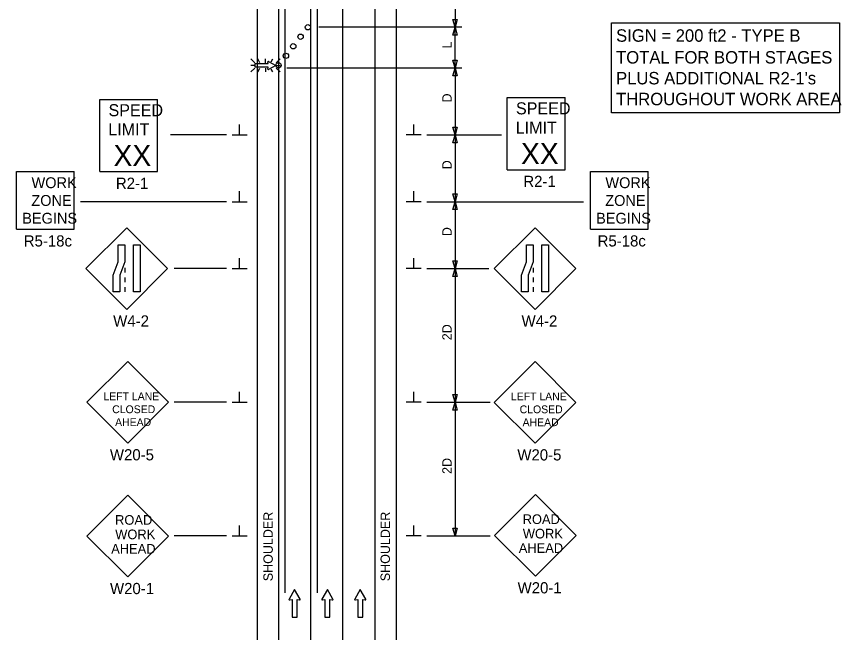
# Model space of a CAD drawing. Extents: x 16782 to 19504, y 6935 to 8243.
# Drawn here: x 16795 to 17412, y 7395 to 7856 of the extents above; entities that cross this region are included whole.
import ezdxf

# ---------------------------------------------------------------- set-up
doc = ezdxf.new("R2010")
doc.units = 0
for name, color, linetype in [('ALI_LEGAL_EX', 7, 'Continuous'), ('MT_SCRATCH_LEVEL_E', 7, 'Continuous'), ('PAVT_EDGE_EX', 7, 'Continuous'), ('TRAFFIC_SIGNS_PR', 7, 'Continuous'), ('TYPICAL_TEXT_DIMEN_EX', 7, 'Continuous'), ('TYPICAL_TEXT_DIMEN_PR', 7, 'Continuous')]:
    doc.layers.add(name, color=color, linetype=linetype)

msp = doc.modelspace()

# ---------------------------------------------------------------- linework, layer by layer
at = {"layer": 'ALI_LEGAL_EX'}
for p, q in [((16995.95, 8243.16), (16995.95, 7425.02)), ((17019.95, 8243.16), (17019.95, 7425.02))]:
    msp.add_line(p, q, dxfattribs=at)
for points in [[(17015.15, 7783.87), (17015.15, 7758.87)], [(17039.15, 7758.87), (17039.15, 7783.87)], [(17015.15, 7683.87), (17015.15, 7658.87)], [(17039.15, 7658.87), (17039.15, 7683.87)], [(17015.15, 7583.87), (17015.15, 7558.87)], [(17039.15, 7558.87), (17039.15, 7583.87)], [(17015.15, 7483.87), (17015.15, 7458.87)], [(17039.15, 7458.87), (17039.15, 7483.87)]]:
    msp.add_lwpolyline(points, dxfattribs=at)
at = {"layer": 'MT_SCRATCH_LEVEL_E'}
for p, q in [((17003.12, 7427.51), (16999.01, 7420.27)), ((17007.27, 7420.27), (17003.12, 7427.51)), ((17027.68, 7427.51), (17023.57, 7420.27)), ((17031.83, 7420.27), (17027.68, 7427.51)), ((17052.24, 7427.51), (17048.13, 7420.27)), ((17056.39, 7420.27), (17052.24, 7427.51)), ((16999.49, 7419.59), (17001.27, 7419.9)), ((17001.27, 7419.9), (17001.27, 7406.65)), ((17005.01, 7406.65), (17005.01, 7419.9)), ((17005.01, 7419.9), (17006.79, 7419.59)), ((17024.05, 7419.59), (17025.83, 7419.9)), ((17025.83, 7419.9), (17025.83, 7406.65)), ((17029.57, 7406.65), (17029.57, 7419.9)), ((17029.57, 7419.9), (17031.35, 7419.59)), ((17048.61, 7419.59), (17050.39, 7419.9)), ((17050.39, 7419.9), (17050.39, 7406.65)), ((17054.13, 7406.65), (17054.13, 7419.9)), ((17054.13, 7419.9), (17055.91, 7419.59)), ((17001.27, 7406.65), (17005.01, 7406.65)), ((17025.83, 7406.65), (17029.57, 7406.65)), ((17050.39, 7406.65), (17054.13, 7406.65))]:
    msp.add_line(p, q, dxfattribs=at)
for centre, start, end in [((16999.42, 7420.05), 150.42484, 279.96381), ((17006.86, 7420.05), 260.03619, 29.77312), ((17023.98, 7420.05), 150.42484, 279.96381), ((17031.42, 7420.05), 260.03619, 29.77312), ((17048.54, 7420.05), 150.42484, 279.96381), ((17055.98, 7420.05), 260.03619, 29.77312)]:
    msp.add_arc(centre, 0.463, start, end, dxfattribs=at)
at = {"layer": 'PAVT_EDGE_EX'}
for p, q in [((16975.15, 8208.67), (16975.15, 7354.69)), ((16991.15, 8208.67), (16991.15, 7354.69)), ((17063.15, 8208.67), (17063.15, 7354.69)), ((17079.15, 8208.67), (17079.15, 7354.69)), ((17015.15, 8183.87), (17015.15, 7354.69)), ((17039.15, 7358.87), (17039.15, 8183.87))]:
    msp.add_line(p, q, dxfattribs=at)
at = {"layer": 'TRAFFIC_SIGNS_PR'}
for p, q in [((16973.31, 7821.47), (16970.49, 7824.29)), ((16977.26, 7821.47), (16975.64, 7824.28)), ((16981.4, 7821.47), (16981.4, 7824.28)), ((16985.58, 7822.1), (16986.84, 7824.28)), ((16992.3, 7824.28), (16989.49, 7821.47)), ((16973.31, 7819.43), (16970.49, 7819.43)), ((16973.31, 7817.4), (16970.49, 7814.58)), ((16975.61, 7814.58), (16977.24, 7817.4)), ((16981.4, 7817.4), (16981.4, 7814.58)), ((16986.87, 7814.58), (16985.66, 7816.67)), ((16989.49, 7819.43), (16992.3, 7819.43)), ((16992.3, 7814.58), (16989.49, 7817.4)), ((16857.53, 7794.02), (16900.73, 7794.02)), ((16857.53, 7740.02), (16857.53, 7794.02)), ((16900.73, 7740.02), (16900.73, 7794.02)), ((17162.19, 7795.41), (17205.39, 7795.41)), ((17162.19, 7741.41), (17162.19, 7795.41)), ((17205.39, 7741.41), (17205.39, 7795.41)), ((16795.22, 7696.88), (16795.22, 7740.08)), ((16795.22, 7740.08), (16838.42, 7740.08)), ((16838.42, 7696.88), (16838.42, 7740.08)), ((16857.53, 7740.02), (16900.73, 7740.02)), ((17162.19, 7741.41), (17205.39, 7741.41)), ((17224.31, 7696.88), (17224.31, 7740.08)), ((17224.31, 7740.08), (17267.51, 7740.08)), ((17267.51, 7696.88), (17267.51, 7740.08)), ((16795.22, 7696.88), (16838.42, 7696.88)), ((16877.68, 7698.1), (16847.14, 7667.55)), ((16908.23, 7667.55), (16877.68, 7698.1)), ((17183.04, 7698.05), (17152.49, 7667.5)), ((17213.58, 7667.5), (17183.04, 7698.05)), ((17224.31, 7696.88), (17267.51, 7696.88)), ((16876.28, 7668.1), (16876.28, 7664.5)), ((17181.63, 7668.05), (17181.63, 7664.45)), ((16847.14, 7667.55), (16877.68, 7637)), ((16877.68, 7637), (16908.23, 7667.55)), ((17152.49, 7667.5), (17183.04, 7636.95)), ((17183.04, 7636.95), (17213.58, 7667.5)), ((16876.28, 7660.9), (16876.28, 7657.3)), ((17181.63, 7660.85), (17181.63, 7657.25)), ((16876.28, 7653.7), (16876.28, 7650.1)), ((17181.63, 7653.65), (17181.63, 7650.05)), ((16878.35, 7598), (16847.8, 7567.45)), ((16908.89, 7567.45), (16878.35, 7598)), ((17183.02, 7597.93), (17152.47, 7567.38)), ((17213.57, 7567.38), (17183.02, 7597.93)), ((16847.8, 7567.45), (16878.35, 7536.9)), ((16878.35, 7536.9), (16908.89, 7567.45)), ((17152.47, 7567.38), (17183.02, 7536.83)), ((17183.02, 7536.83), (17213.57, 7567.38)), ((16878.44, 7497.94), (16847.89, 7467.39)), ((16908.98, 7467.39), (16878.44, 7497.94)), ((17183.22, 7498.49), (17152.67, 7467.94)), ((17213.76, 7467.94), (17183.22, 7498.49)), ((16847.89, 7467.39), (16878.44, 7436.85)), ((16878.44, 7436.85), (16908.98, 7467.39)), ((17152.67, 7467.94), (17183.22, 7437.4)), ((17183.22, 7437.4), (17213.76, 7467.94))]:
    msp.add_line(p, q, dxfattribs=at)
for points in [[(16983.73, 7822.45), (16989.04, 7819.43), (16983.73, 7816.39)], [(16983.23, 7816.75), (16983.46, 7818.05), (16973.73, 7818.05), (16973.73, 7820.79), (16983.46, 7820.79), (16983.22, 7822.09)]]:
    msp.add_lwpolyline(points, dxfattribs=at)
for points in [[(16876.28, 7685.25), (16876.28, 7672.67), (16872.52, 7662.68), (16872.52, 7650.1), (16867.46, 7650.1), (16867.46, 7662.68), (16871.23, 7672.67), (16871.23, 7685.25)], [(16887.68, 7685.25), (16887.68, 7650.1), (16882.63, 7650.1), (16882.63, 7685.25)], [(17181.63, 7685.21), (17181.63, 7672.63), (17177.87, 7662.63), (17177.87, 7650.05), (17172.81, 7650.05), (17172.81, 7662.63), (17176.58, 7672.63), (17176.58, 7685.21)], [(17193.04, 7685.21), (17193.04, 7650.05), (17187.98, 7650.05), (17187.98, 7685.21)]]:
    msp.add_lwpolyline(points, close=True, dxfattribs=at)
for centre in [(17013.14, 7848.04), (17013.14, 7848.04), (17013.14, 7848.04), (17013.14, 7848.04), (17007.65, 7840.91), (17002.15, 7833.78), (16996.65, 7826.65), (16991.15, 7819.53)]:
    msp.add_circle(centre, 2, dxfattribs=at)
for centre, start, end in [((16983.56, 7822.15), 61.10835, 189.26922), ((16983.56, 7816.69), 170.04067, 298.51671)]:
    msp.add_arc(centre, 0.341, start, end, dxfattribs=at)
at = {"layer": 'TYPICAL_TEXT_DIMEN_EX'}
msp.add_lwpolyline([(17240.11, 7851.23), (17410.53, 7851.23), (17410.53, 7784.05), (17240.11, 7784.05)], close=True, dxfattribs=at)
at = {"layer": 'TYPICAL_TEXT_DIMEN_PR'}
for p, q in [((17123.24, 7940.1), (17123.15, 7848.04)), ((17123.15, 7848.04), (17121.58, 7853.9)), ((17121.58, 7853.9), (17123.15, 7853.9)), ((17123.15, 7853.9), (17124.72, 7853.9)), ((17124.72, 7853.9), (17123.15, 7848.04)), ((17128.15, 7848.04), (17021.23, 7848.04)), ((17121.58, 7842.18), (17123.15, 7848.04)), ((17123.15, 7817.53), (17123.15, 7848.04)), ((17123.15, 7848.04), (17124.72, 7842.18)), ((17123.15, 7842.18), (17121.58, 7842.18)), ((17124.72, 7842.18), (17123.15, 7842.18)), ((17123.15, 7817.53), (17121.58, 7823.39)), ((17121.58, 7823.39), (17123.15, 7823.39)), ((17123.15, 7823.39), (17124.72, 7823.39)), ((17124.72, 7823.39), (17123.15, 7817.53)), ((17128.15, 7817.53), (16997.42, 7817.53)), ((17121.58, 7811.67), (17123.15, 7817.53)), ((17123.15, 7817.53), (17123.15, 7767.53)), ((17123.15, 7817.53), (17124.72, 7811.67)), ((17123.15, 7811.67), (17121.58, 7811.67)), ((17124.72, 7811.67), (17123.15, 7811.67)), ((16962.03, 7767.53), (16962.03, 7775.31)), ((17092.28, 7767.53), (17092.28, 7775.31)), ((17123.15, 7767.53), (17121.58, 7773.39)), ((17121.58, 7773.39), (17123.15, 7773.39)), ((17123.15, 7773.39), (17124.72, 7773.39)), ((17124.72, 7773.39), (17123.15, 7767.53)), ((16952.15, 7767.53), (16910.46, 7767.53)), ((16956.4, 7767.53), (16967.65, 7767.53)), ((17097.9, 7767.53), (17086.65, 7767.53)), ((17102.15, 7767.53), (17157.89, 7767.53)), ((17121.58, 7761.67), (17123.15, 7767.53)), ((17123.15, 7767.53), (17124.72, 7761.67)), ((17123.15, 7767.53), (17123.15, 7717.53)), ((17123.15, 7761.67), (17121.58, 7761.67)), ((17124.72, 7761.67), (17123.15, 7761.67)), ((16962.03, 7717.53), (16962.03, 7725.31)), ((17092.28, 7717.53), (17092.28, 7725.31)), ((16952.15, 7717.53), (16843.19, 7717.53)), ((16956.4, 7717.53), (16967.65, 7717.53)), ((17097.9, 7717.53), (17086.65, 7717.53)), ((17102.15, 7717.53), (17219.11, 7717.53)), ((17123.15, 7717.53), (17121.58, 7723.39)), ((17121.58, 7723.39), (17123.15, 7723.39)), ((17121.58, 7711.67), (17123.15, 7717.53)), ((17123.15, 7723.39), (17124.72, 7723.39)), ((17124.72, 7723.39), (17123.15, 7717.53)), ((17123.15, 7717.53), (17124.72, 7711.67)), ((17123.15, 7717.53), (17123.15, 7667.53)), ((17123.15, 7711.67), (17121.58, 7711.67)), ((17124.72, 7711.67), (17123.15, 7711.67)), ((16962.03, 7667.53), (16962.03, 7675.31)), ((17092.28, 7667.53), (17092.28, 7675.31)), ((17123.15, 7667.53), (17121.58, 7673.39)), ((17121.58, 7673.39), (17123.15, 7673.39)), ((17123.15, 7673.39), (17124.72, 7673.39)), ((17124.72, 7673.39), (17123.15, 7667.53)), ((16952.15, 7667.53), (16913.15, 7667.53)), ((16956.4, 7667.53), (16967.65, 7667.53)), ((17097.9, 7667.53), (17086.65, 7667.53)), ((17102.15, 7667.53), (17148.41, 7667.53)), ((17121.58, 7661.67), (17123.15, 7667.53)), ((17123.15, 7667.53), (17123.15, 7567.53)), ((17123.15, 7667.53), (17124.72, 7661.67)), ((17123.15, 7661.67), (17121.58, 7661.67)), ((17124.72, 7661.67), (17123.15, 7661.67)), ((16962.03, 7567.53), (16962.03, 7575.31)), ((17092.28, 7567.53), (17092.28, 7575.31)), ((17123.15, 7567.53), (17121.58, 7573.39)), ((17121.58, 7573.39), (17123.15, 7573.39)), ((17123.15, 7573.39), (17124.72, 7573.39)), ((17124.72, 7573.39), (17123.15, 7567.53)), ((16952.15, 7567.53), (16913.15, 7567.53)), ((16956.4, 7567.53), (16967.65, 7567.53)), ((17097.9, 7567.53), (17086.65, 7567.53)), ((17102.15, 7567.53), (17149.45, 7567.53)), ((17121.58, 7561.67), (17123.15, 7567.53)), ((17123.15, 7567.53), (17123.15, 7467.53)), ((17123.15, 7567.53), (17124.72, 7561.67)), ((17123.15, 7561.67), (17121.58, 7561.67)), ((17124.72, 7561.67), (17123.15, 7561.67)), ((16962.03, 7467.53), (16962.03, 7475.31)), ((17092.28, 7467.53), (17092.28, 7475.31)), ((17123.15, 7467.53), (17121.58, 7473.39)), ((17121.58, 7473.39), (17123.15, 7473.39)), ((17123.15, 7473.39), (17124.72, 7473.39)), ((17124.72, 7473.39), (17123.15, 7467.53)), ((16952.15, 7467.53), (16913.15, 7467.53)), ((16956.4, 7467.53), (16967.65, 7467.53)), ((17097.9, 7467.53), (17086.65, 7467.53)), ((17102.15, 7467.53), (17149.45, 7467.53))]:
    msp.add_line(p, q, dxfattribs=at)

# ---------------------------------------------------------------- texts
at = {"layer": 'TRAFFIC_SIGNS_PR'}
for s, height, p in [('SPEED', 9, (17168.68, 7782.87)), ('SPEED', 9, (16864.02, 7781.49)), ('LIMIT', 9, (16863.84, 7767.09)), ('LIMIT', 9, (17168.5, 7768.47)), ('XX', 15.785, (17172.44, 7745.63)), ('XX', 15.785, (16867.78, 7744.25)), ('WORK', 8.119, (16806.46, 7727.67)), ('R2-1', 8.37, (17174.2, 7728.54)), ('WORK', 8.119, (17235.56, 7727.67)), ('R2-1', 8.37, (16869.54, 7727.15)), ('ZONE', 8.119, (16806.33, 7714.38)), ('ZONE', 8.119, (17235.43, 7714.38)), ('BEGINS', 8.119, (16799.5, 7701.1)), ('BEGINS', 8.119, (17228.6, 7701.1)), ('R5-18c', 8.37, (16800.63, 7684.01)), ('R5-18c', 8.37, (17229.73, 7684.01)), ('W4-2', 8.37, (16867.51, 7624.13)), ('W4-2', 8.37, (17172.86, 7624.09)), ('LEFT LANE', 5.85, (16860.21, 7569.02)), ('LEFT LANE', 5.85, (17164.89, 7568.95)), ('CLOSED', 5.85, (16866.77, 7559.34)), ('CLOSED', 5.85, (17171.45, 7559.27)), ('AHEAD', 5.85, (16868.96, 7549.67)), ('AHEAD', 5.85, (17173.64, 7549.6)), ('W20-5', 8.37, (16865.04, 7524.03)), ('W20-5', 8.37, (17169.71, 7523.96)), ('ROAD', 7.2, (16868.92, 7475.87)), ('ROAD', 7.2, (17173.7, 7476.42)), ('WORK', 7.2, (16869.04, 7465.07)), ('WORK', 7.2, (17173.82, 7465.62)), ('AHEAD', 7.2, (16866.02, 7454.27)), ('AHEAD', 7.2, (17170.8, 7454.82)), ('W20-1', 8.37, (16865.13, 7423.98)), ('W20-1', 8.37, (17169.91, 7424.53))]:
    msp.add_text(s, height=height, dxfattribs=at).set_placement(p)
at = {"layer": 'TYPICAL_TEXT_DIMEN_EX'}
for s, p in [('SIGN = 200 ft2 - TYPE B', (17243.55, 7837.19)), ('TOTAL FOR BOTH STAGES', (17243.55, 7820.89)), ("PLUS ADDITIONAL R2-1's", (17243.55, 7805.29)), ('THROUGHOUT WORK AREA', (17243.55, 7789.69))]:
    msp.add_text(s, height=9.3, dxfattribs=at).set_placement(p)
at = {"layer": 'TYPICAL_TEXT_DIMEN_PR'}
for s, p in [('L', (17120.59, 7832.14)), ('D', (17120.59, 7791.75)), ('D', (17120.59, 7741.75)), ('D', (17120.59, 7691.75)), ('2D', (17120.59, 7613.89)), ('2D', (17120.59, 7513.89)), ('SHOULDER', (16986.84, 7433.62)), ('SHOULDER', (17074.43, 7433.62))]:
    msp.add_text(s, height=7, rotation=90, dxfattribs=at).set_placement(p)

doc.saveas('drawing.dxf')
